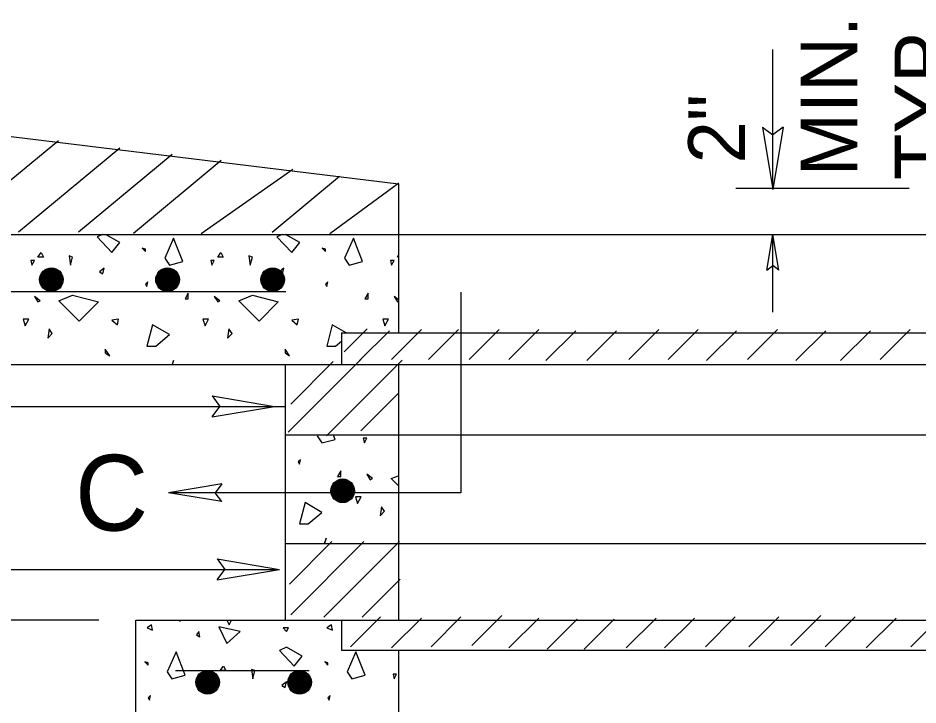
# Model space of a CAD drawing. Extents: x 5.8 to 18, y -5.2 to 5.4.
# Drawn here: x 6.755 to 7.706, y -0.7 to 0.026 of the extents above; entities that cross this region are included whole.
import ezdxf

# ---------------------------------------------------------------- set-up
doc = ezdxf.new("R2010")
doc.units = 0
for name, color, linetype in [('DETL-DIMS', 7, 'Continuous'), ('DETL-LINE', 7, 'Continuous'), ('DETL-NOTE', 7, 'Continuous'), ('DETL-PATT', 7, 'Continuous')]:
    doc.layers.add(name, color=color, linetype=linetype)

msp = doc.modelspace()

# ---------------------------------------------------------------- linework, layer by layer
at = {"layer": 'DETL-DIMS'}
for p, q in [((7.55235, -0.15546), (7.55235, -0.00753)), ((7.54137, -0.08957), (7.55235, -0.15546)), ((7.54137, -0.08957), (7.55235, -0.09781)), ((7.56333, -0.08957), (7.55235, -0.15546)), ((7.56333, -0.08957), (7.55235, -0.09781)), ((7.69639, -0.15436), (7.51314, -0.15436)), ((7.54608, -0.24044), (7.55235, -0.20279)), ((7.55235, -0.28479), (7.55235, -0.20279)), ((7.55863, -0.24044), (7.55235, -0.20279)), ((7.54608, -0.24044), (7.55235, -0.23573)), ((7.55863, -0.24044), (7.55235, -0.23573)), ((7.22275, -0.26381), (7.22275, -0.47561)), ((6.95984, -0.37342), (7.02573, -0.3844)), ((6.95984, -0.37342), (6.96808, -0.3844)), ((6.70086, -0.3844), (7.03698, -0.3844)), ((6.95984, -0.39538), (7.02573, -0.3844)), ((6.95984, -0.39538), (6.96808, -0.3844)), ((6.97004, -0.4662), (6.91357, -0.47561)), ((6.97004, -0.4662), (6.96298, -0.47561)), ((7.22275, -0.47561), (6.91357, -0.47561)), ((6.97004, -0.48502), (6.91357, -0.47561)), ((6.97004, -0.48502), (6.96298, -0.47561)), ((6.96502, -0.54557), (7.0309, -0.55655)), ((6.96502, -0.54557), (6.97325, -0.55655)), ((6.70086, -0.55655), (7.0309, -0.55655)), ((6.96502, -0.56753), (7.0309, -0.55655)), ((6.96502, -0.56753), (6.97325, -0.55655)), ((6.83992, -0.61012), (6.57824, -0.61012))]:
    msp.add_line(p, q, dxfattribs=at)
at = {"layer": 'DETL-LINE'}
for p, q in [((7.15675, -0.14993), (6.404, -0.05765)), ((7.15675, -0.14993), (7.15675, -0.30671)), ((6.404, -0.20279), (8.5262, -0.20279)), ((6.34345, -0.2631), (7.03776, -0.2631)), ((7.09643, -0.30671), (7.80416, -0.30671)), ((7.09643, -0.30671), (7.09643, -0.34028)), ((6.26486, -0.34028), (7.03698, -0.34028)), ((7.03698, -0.34028), (8.65804, -0.34028)), ((7.03698, -0.34028), (7.03698, -0.61012)), ((7.15675, -0.34028), (7.15675, -0.61012)), ((7.86275, -0.41498), (7.03698, -0.41498)), ((7.86275, -0.52942), (7.03698, -0.52942)), ((6.87914, -0.61012), (8.0651, -0.61012)), ((6.87914, -2.13177), (6.87914, -0.61012)), ((7.09643, -0.61012), (7.09643, -0.64173)), ((7.09643, -0.64173), (7.80416, -0.64173)), ((7.15675, -0.64173), (7.15675, -0.73934)), ((6.92118, -0.66334), (7.0622, -0.66334))]:
    msp.add_line(p, q, dxfattribs=at)
msp.add_lwpolyline([(6.96106, -0.66718), (6.96216, -0.67197), (6.96471, -0.66718)], close=True, dxfattribs=at)
for centre, radius in [((6.78996, -0.25064), 0.01247), ((6.78985, -0.25053), 0.01163), ((6.78874, -0.25053), 0.01009), ((6.78999, -0.25083), 0.01122), ((6.79032, -0.25136), 0.011), ((6.79027, -0.25096), 0.01024), ((6.78915, -0.25004), 0.00834), ((6.79054, -0.25102), 0.00969), ((6.79062, -0.2513), 0.00918), ((6.78895, -0.25102), 0.00724), ((6.79076, -0.25143), 0.00876), ((6.79062, -0.25165), 0.00835), ((6.78832, -0.25143), 0.00578), ((6.79083, -0.25165), 0.00814), ((6.79068, -0.25151), 0.00786), ((6.79103, -0.25171), 0.00751), ((6.79111, -0.25157), 0.00704), ((6.78929, -0.25116), 0.00467), ((6.79117, -0.25149), 0.00655), ((6.79117, -0.25136), 0.006), ((6.79125, -0.25151), 0.00565), ((6.79125, -0.25157), 0.0051), ((6.79146, -0.252), 0.00488), ((6.91271, -0.25064), 0.01247), ((6.9126, -0.25053), 0.01163), ((6.91148, -0.25053), 0.01009), ((6.91274, -0.25083), 0.01122), ((6.91307, -0.25136), 0.011), ((6.91301, -0.25096), 0.01024), ((6.91189, -0.25004), 0.00834), ((6.91329, -0.25102), 0.00969), ((6.91336, -0.2513), 0.00918), ((6.9117, -0.25102), 0.00724), ((6.9135, -0.25143), 0.00876), ((6.91336, -0.25165), 0.00835), ((6.91107, -0.25143), 0.00578), ((6.91358, -0.25165), 0.00814), ((6.91342, -0.25151), 0.00786), ((6.91378, -0.25171), 0.00751), ((6.91385, -0.25157), 0.00704), ((6.91391, -0.25149), 0.00655), ((6.91203, -0.25116), 0.00467), ((6.91391, -0.25136), 0.006), ((6.91399, -0.25151), 0.00565), ((6.91399, -0.25157), 0.0051), ((6.91421, -0.252), 0.00488), ((7.02376, -0.25064), 0.01247), ((7.02366, -0.25053), 0.01163), ((7.02254, -0.25053), 0.01009), ((7.0238, -0.25083), 0.01122), ((7.02413, -0.25136), 0.011), ((7.02407, -0.25096), 0.01024), ((7.02295, -0.25004), 0.00834), ((7.02434, -0.25102), 0.00969), ((7.02442, -0.2513), 0.00918), ((7.02276, -0.25102), 0.00724), ((7.02456, -0.25143), 0.00876), ((7.02442, -0.25165), 0.00835), ((7.02213, -0.25143), 0.00578), ((7.02464, -0.25165), 0.00814), ((7.02448, -0.25151), 0.00786), ((7.02483, -0.25171), 0.00751), ((7.02491, -0.25157), 0.00704), ((7.02497, -0.25149), 0.00655), ((7.02309, -0.25116), 0.00467), ((7.02497, -0.25136), 0.006), ((7.02505, -0.25151), 0.00565), ((7.02505, -0.25157), 0.0051), ((7.02527, -0.252), 0.00488), ((6.79158, -0.25206), 0.00445), ((6.79158, -0.25194), 0.0039), ((6.79174, -0.25185), 0.00377), ((6.79174, -0.2522), 0.00347), ((6.79187, -0.25192), 0.00333), ((6.79193, -0.252), 0.00285), ((6.79174, -0.25179), 0.00238), ((6.79201, -0.25208), 0.00212), ((6.79209, -0.25206), 0.00175), ((6.79223, -0.25214), 0.00133), ((6.79223, -0.252), 0.00118), ((6.79264, -0.25206), 0.00148), ((6.79221, -0.252), 0.000769), ((6.79207, -0.252), 0.000362), ((6.79236, -0.252), 0.00023), ((6.91432, -0.25206), 0.00445), ((6.91432, -0.25194), 0.0039), ((6.91448, -0.25185), 0.00377), ((6.91448, -0.2522), 0.00347), ((6.91462, -0.25192), 0.00333), ((6.91468, -0.252), 0.00285), ((6.91448, -0.25179), 0.00238), ((6.91476, -0.25208), 0.00212), ((6.91483, -0.25206), 0.00175), ((6.91497, -0.25214), 0.00133), ((6.91497, -0.252), 0.00118), ((6.91538, -0.25206), 0.00148), ((6.91495, -0.252), 0.000769), ((6.91481, -0.252), 0.000362), ((6.91511, -0.252), 0.00023), ((7.02538, -0.25206), 0.00445), ((7.02538, -0.25194), 0.0039), ((7.02554, -0.25185), 0.00377), ((7.02554, -0.2522), 0.00347), ((7.02568, -0.25192), 0.00333), ((7.02574, -0.252), 0.00285), ((7.02554, -0.25179), 0.00238), ((7.02581, -0.25208), 0.00212), ((7.02589, -0.25206), 0.00175), ((7.02603, -0.25214), 0.00133), ((7.02603, -0.252), 0.00118), ((7.02644, -0.25206), 0.00148), ((7.02601, -0.252), 0.000769), ((7.02587, -0.252), 0.000362), ((7.02617, -0.252), 0.00023), ((7.09776, -0.47357), 0.01247), ((7.09766, -0.47346), 0.01163), ((7.09654, -0.47346), 0.01009), ((7.0978, -0.47376), 0.01122), ((7.09813, -0.47429), 0.011), ((7.09807, -0.4739), 0.01024), ((7.09695, -0.47297), 0.00834), ((7.09834, -0.47395), 0.00969), ((7.09842, -0.47423), 0.00918), ((7.09856, -0.47437), 0.00876), ((7.09676, -0.47395), 0.00724), ((7.09842, -0.47458), 0.00835), ((7.09613, -0.47437), 0.00578), ((7.09864, -0.47458), 0.00814), ((7.09848, -0.47444), 0.00786), ((7.09883, -0.47464), 0.00751), ((7.09891, -0.4745), 0.00704), ((7.09897, -0.47442), 0.00655), ((7.09709, -0.47409), 0.00467), ((7.09897, -0.47429), 0.006), ((7.09905, -0.47444), 0.00565), ((7.09905, -0.4745), 0.0051), ((7.09927, -0.47493), 0.00488), ((7.09938, -0.47499), 0.00445), ((7.09938, -0.47488), 0.0039), ((7.09954, -0.47478), 0.00377), ((7.09954, -0.47513), 0.00347), ((7.09968, -0.47486), 0.00333), ((7.09974, -0.47493), 0.00285), ((7.09954, -0.47472), 0.00238), ((7.09981, -0.47501), 0.00212), ((7.09989, -0.47499), 0.00175), ((7.10003, -0.47507), 0.00133), ((7.10003, -0.47493), 0.00118), ((7.10044, -0.47499), 0.00148), ((7.10001, -0.47493), 0.000769), ((7.09987, -0.47493), 0.000362), ((7.10017, -0.47493), 0.00023), ((6.95506, -0.6758), 0.01247), ((6.95495, -0.6757), 0.01163), ((6.95383, -0.6757), 0.01009), ((6.95509, -0.67599), 0.01122), ((6.95542, -0.67652), 0.011), ((7.05224, -0.6758), 0.01247), ((7.05213, -0.6757), 0.01163), ((7.05101, -0.6757), 0.01009), ((7.05227, -0.67599), 0.01122), ((7.0526, -0.67652), 0.011), ((6.95536, -0.67613), 0.01024), ((6.95425, -0.67521), 0.00834), ((6.95564, -0.67619), 0.00969), ((6.95572, -0.67646), 0.00918), ((6.95405, -0.67619), 0.00724), ((6.95585, -0.6766), 0.00876), ((6.95572, -0.67682), 0.00835), ((6.95342, -0.6766), 0.00578), ((6.95593, -0.67682), 0.00814), ((6.95578, -0.67668), 0.00786), ((6.95613, -0.67688), 0.00751), ((6.95621, -0.67674), 0.00704), ((6.95438, -0.67633), 0.00467), ((6.95627, -0.67666), 0.00655), ((6.95627, -0.67652), 0.006), ((6.95634, -0.67668), 0.00565), ((6.95634, -0.67674), 0.0051), ((6.95656, -0.67717), 0.00488), ((6.95668, -0.67723), 0.00445), ((6.95668, -0.67711), 0.0039), ((6.95683, -0.67701), 0.00377), ((6.95683, -0.67737), 0.00347), ((6.95697, -0.67709), 0.00333), ((6.95703, -0.67717), 0.00285), ((6.95683, -0.67695), 0.00238), ((6.95711, -0.67725), 0.00212), ((7.05254, -0.67613), 0.01024), ((7.05142, -0.67521), 0.00834), ((7.05281, -0.67619), 0.00969), ((7.05289, -0.67646), 0.00918), ((7.05123, -0.67619), 0.00724), ((7.05303, -0.6766), 0.00876), ((7.05289, -0.67682), 0.00835), ((7.0506, -0.6766), 0.00578), ((7.05311, -0.67682), 0.00814), ((7.05295, -0.67668), 0.00786), ((7.05331, -0.67688), 0.00751), ((7.05338, -0.67674), 0.00704), ((7.05344, -0.67666), 0.00655), ((7.05156, -0.67633), 0.00467), ((7.05344, -0.67652), 0.006), ((7.05352, -0.67668), 0.00565), ((7.05352, -0.67674), 0.0051), ((7.05374, -0.67717), 0.00488), ((7.05385, -0.67723), 0.00445), ((7.05385, -0.67711), 0.0039), ((7.05401, -0.67701), 0.00377), ((7.05401, -0.67737), 0.00347), ((7.05415, -0.67709), 0.00333), ((7.05421, -0.67717), 0.00285), ((7.05401, -0.67695), 0.00238), ((7.05429, -0.67725), 0.00212), ((6.95719, -0.67723), 0.00175), ((6.95732, -0.67731), 0.00133), ((6.95732, -0.67717), 0.00118), ((6.95774, -0.67723), 0.00148), ((6.95731, -0.67717), 0.000769), ((6.95717, -0.67717), 0.000362), ((6.95746, -0.67717), 0.00023), ((7.05436, -0.67723), 0.00175), ((7.0545, -0.67731), 0.00133), ((7.0545, -0.67717), 0.00118), ((7.05491, -0.67723), 0.00148), ((7.05448, -0.67717), 0.000769), ((7.05434, -0.67717), 0.000362), ((7.05464, -0.67717), 0.00023)]:
    msp.add_circle(centre, radius, dxfattribs=at)
at = {"layer": 'DETL-PATT'}
for p, q in [((6.67859, -0.20169), (6.79729, -0.10353)), ((6.75514, -0.20024), (6.86243, -0.11149)), ((6.81855, -0.20012), (6.91753, -0.11828)), ((6.87675, -0.20138), (6.96953, -0.12463)), ((6.94816, -0.20177), (7.04525, -0.13408)), ((7.02329, -0.20032), (7.09451, -0.14142)), ((7.08431, -0.20204), (7.15694, -0.14832)), ((7.09945, -0.32671), (7.12373, -0.30244)), ((7.14933, -0.33483), (7.18098, -0.30318)), ((7.18843, -0.33483), (7.22008, -0.30318)), ((7.23157, -0.33483), (7.26322, -0.30318)), ((7.27337, -0.33483), (7.30502, -0.30318)), ((7.40012, -0.33483), (7.43176, -0.30318)), ((7.44188, -0.33483), (7.47353, -0.30318)), ((7.52549, -0.33483), (7.55714, -0.30318)), ((7.66573, -0.33483), (7.69737, -0.30318)), ((7.11561, -0.33616), (7.14725, -0.30451)), ((7.31247, -0.33616), (7.34412, -0.30451)), ((7.35561, -0.33616), (7.38725, -0.30451)), ((7.48235, -0.33616), (7.514, -0.30451)), ((7.57675, -0.33616), (7.60839, -0.30451)), ((7.62392, -0.33616), (7.65557, -0.30451)), ((7.04012, -0.41169), (7.11737, -0.33444)), ((7.04282, -0.38197), (7.08769, -0.3371)), ((7.08055, -0.41569), (7.16047, -0.33577)), ((7.11694, -0.41028), (7.15725, -0.36997)), ((7.04145, -0.57208), (7.08631, -0.52722)), ((7.04282, -0.60448), (7.12008, -0.52722)), ((7.07788, -0.60714), (7.1578, -0.52722)), ((7.11831, -0.60714), (7.15863, -0.56683)), ((7.1062, -0.6382), (7.13784, -0.60655)), ((7.14933, -0.63953), (7.18098, -0.60789)), ((7.19114, -0.6382), (7.22278, -0.60655)), ((7.23427, -0.63683), (7.26592, -0.60518)), ((7.27337, -0.63953), (7.30502, -0.60789)), ((7.39741, -0.63953), (7.42906, -0.60789)), ((7.43788, -0.63953), (7.46953, -0.60789)), ((7.48102, -0.6382), (7.51267, -0.60655)), ((7.52686, -0.6382), (7.55851, -0.60655)), ((7.57137, -0.63683), (7.60302, -0.60518)), ((7.60776, -0.6382), (7.63941, -0.60655)), ((7.6509, -0.63953), (7.68255, -0.60789)), ((7.69808, -0.6382), (7.72973, -0.60655)), ((7.09643, -0.61012), (7.09643, -0.64173)), ((7.31384, -0.64091), (7.34549, -0.60926)), ((7.35294, -0.64091), (7.38459, -0.60926))]:
    msp.add_line(p, q, dxfattribs=at)
for points in [[(6.8438, -0.20279), (6.83835, -0.2053), (6.85388, -0.22197), (6.86235, -0.21153), (6.84722, -0.20279)], [(7.0338, -0.20279), (7.02835, -0.2053), (7.04388, -0.22197), (7.05235, -0.21153), (7.03722, -0.20279)], [(7.15675, -0.22675), (7.15569, -0.22675), (7.15675, -0.2253)], [(7.15675, -0.27208), (7.15204, -0.26828), (7.15569, -0.2742), (7.15675, -0.27369)], [(7.10129, -0.30671), (7.08682, -0.2982), (7.08086, -0.32079), (7.0902, -0.32079), (7.09643, -0.31553)], [(6.91808, -0.34028), (6.9191, -0.33604), (6.91761, -0.34028)], [(7.07125, -0.41498), (7.07098, -0.41557), (7.07576, -0.42295), (7.08988, -0.41926), (7.08824, -0.41498)], [(7.15675, -0.46832), (7.14918, -0.46075), (7.15675, -0.45765)], [(7.07898, -0.52942), (7.08031, -0.52373), (7.07831, -0.52942)], [(6.92529, -0.61012), (6.92545, -0.61126), (6.92682, -0.61012)], [(6.97541, -0.61012), (6.97769, -0.61495), (6.9802, -0.61012)]]:
    msp.add_lwpolyline(points, dxfattribs=at)
for points in [[(6.91459, -0.23522), (6.92871, -0.23157), (6.9191, -0.20671), (6.90976, -0.22789)], [(7.10459, -0.23522), (7.11871, -0.23157), (7.1091, -0.20671), (7.0998, -0.22789)], [(6.88945, -0.21859), (6.88604, -0.21746), (6.88945, -0.22083)], [(7.07945, -0.21859), (7.07608, -0.21746), (7.07945, -0.22083)], [(6.77906, -0.22197), (6.78157, -0.22675), (6.77565, -0.22675)], [(6.80871, -0.22565), (6.81012, -0.23522), (6.81235, -0.22675)], [(6.96906, -0.22197), (6.97161, -0.22675), (6.96569, -0.22675)], [(6.99871, -0.22565), (7.00012, -0.23522), (7.00239, -0.22675)], [(6.76831, -0.23044), (6.76945, -0.23522), (6.772, -0.23044)], [(6.95835, -0.23044), (6.95945, -0.23522), (6.962, -0.23044)], [(7.14835, -0.23044), (7.14949, -0.23522), (7.15204, -0.23044)], [(6.84086, -0.24228), (6.84427, -0.24455), (6.84569, -0.23863)], [(7.0309, -0.24228), (7.03427, -0.24455), (7.03569, -0.23863)], [(6.892, -0.25302), (6.88945, -0.2553), (6.89086, -0.25781)], [(7.082, -0.25302), (7.07945, -0.2553), (7.08086, -0.25781)], [(6.93463, -0.26487), (6.93122, -0.27083), (6.93463, -0.27083)], [(7.12463, -0.26487), (7.12125, -0.27083), (7.12463, -0.27083)], [(6.77565, -0.2742), (6.77792, -0.27306), (6.772, -0.26828)], [(6.81235, -0.26714), (6.83976, -0.2742), (6.81941, -0.29451), (6.79796, -0.27306)], [(6.96569, -0.2742), (6.96792, -0.27306), (6.962, -0.26828)], [(7.00239, -0.26714), (7.02976, -0.2742), (7.00945, -0.29451), (6.988, -0.27306)], [(6.76012, -0.29228), (6.76239, -0.29934), (6.76604, -0.29228)], [(6.85388, -0.29342), (6.8598, -0.2982), (6.86094, -0.29228)], [(6.95016, -0.29228), (6.95239, -0.29934), (6.95608, -0.29228)], [(7.04388, -0.29342), (7.0498, -0.2982), (7.05094, -0.29228)], [(7.14016, -0.29228), (7.14243, -0.29934), (7.14612, -0.29228)], [(6.78753, -0.30271), (6.78612, -0.31232), (6.7909, -0.30753)], [(6.90016, -0.32079), (6.91459, -0.30863), (6.89678, -0.2982), (6.89086, -0.32079)], [(6.97753, -0.30271), (6.97612, -0.31232), (6.98094, -0.30753)], [(6.84682, -0.32416), (6.84682, -0.32785), (6.85161, -0.33122)], [(7.03682, -0.32416), (7.03682, -0.32785), (7.04165, -0.33122)], [(7.11953, -0.41812), (7.12067, -0.42295), (7.12322, -0.41812)], [(7.05318, -0.44071), (7.05067, -0.44298), (7.05208, -0.44553)], [(7.09584, -0.45259), (7.09243, -0.45851), (7.09584, -0.45851)], [(7.1269, -0.46189), (7.12914, -0.46075), (7.12322, -0.45597)], [(7.11137, -0.47997), (7.11361, -0.48702), (7.11729, -0.47997)], [(7.06137, -0.50848), (7.07576, -0.49636), (7.058, -0.48589), (7.05208, -0.50848)], [(7.13875, -0.4904), (7.13733, -0.5), (7.14212, -0.49522)], [(6.89102, -0.61832), (6.89694, -0.62087), (6.8958, -0.61495)], [(6.96698, -0.61722), (6.97545, -0.63498), (6.98957, -0.622)], [(7.08106, -0.61832), (7.08698, -0.62087), (7.08584, -0.61495)], [(6.94325, -0.62569), (6.94694, -0.62793), (6.9458, -0.622)], [(7.03475, -0.61832), (7.03839, -0.622), (7.04067, -0.61832)], [(6.91729, -0.67197), (6.93141, -0.66832), (6.9218, -0.64346), (6.91247, -0.66463)], [(7.03106, -0.64204), (7.04659, -0.65871), (7.05506, -0.64828), (7.03839, -0.63867)], [(7.10729, -0.67197), (7.12141, -0.66832), (7.1118, -0.64346), (7.10251, -0.66463)], [(6.89216, -0.65534), (6.88875, -0.6542), (6.89216, -0.65757)], [(7.08216, -0.65534), (7.07878, -0.6542), (7.08216, -0.65757)], [(6.97176, -0.65871), (6.97431, -0.66349), (6.96839, -0.66349)], [(7.00141, -0.6624), (7.00282, -0.67197), (7.0051, -0.66349)], [(7.15106, -0.66718), (7.1522, -0.67197), (7.15475, -0.66718)], [(7.03361, -0.67902), (7.03698, -0.6813), (7.03839, -0.67538)], [(6.89471, -0.68977), (6.89216, -0.69204), (6.89357, -0.69455)], [(7.08471, -0.68977), (7.08216, -0.69204), (7.08357, -0.69455)]]:
    msp.add_lwpolyline(points, close=True, dxfattribs=at)

# ---------------------------------------------------------------- texts
at = {"layer": 'DETL-NOTE'}
for s, p in [('MIN.', (7.64176, -0.14153)), ('TYP.', (7.74098, -0.14538)), ('2"', (7.52294, -0.12785))]:
    msp.add_text(s, height=0.06, rotation=90, dxfattribs=at).set_placement(p)
msp.add_text('C', height=0.08, dxfattribs=at).set_placement((6.81494, -0.51561))

doc.saveas('drawing.dxf')
